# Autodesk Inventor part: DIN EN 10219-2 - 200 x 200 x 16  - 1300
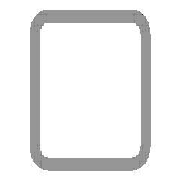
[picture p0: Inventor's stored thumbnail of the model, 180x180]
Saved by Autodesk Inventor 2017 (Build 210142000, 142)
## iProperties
Created: 2017-11
Part Number: DIN EN 10219-2 - 200 x 200 x 16  - 1300
Material: Steel, Mild
Description: Cold formed welded structural hollow sections of non-alloy and fine grain structural steel
Document SubType Name: Modeling
Standard: DIN
Designer: iusti
Standard Revision: 2006-07
Standards Organization: DIN
Language: en-US
Size Designation: 200 x 200 x 16
Categories: <MemberInstance><Categories><Category DisplayName="Structural Shapes" InternalName="089c4875-fa83-4c05-b084-43b9cc11f5ed" Mnemonic="GRDR"><CategoryParameter Dis
Stock Number: 200 x 200 x 16
Mass: 108961 g
Surface Area: 17564.1 cm^2
Volume: 13880.4 cm^3
Density: 7.85 g/cm^3
Appearance: Semi-Polished
G_L: 1300.000 mm
G_W: 200.000 mm
G_H: 200.000 mm
+256F9982-8F43-4545-88E3-061E3400206B+CUTDETAIL1: Cut
+92690F86-3DA3-4326-AD70-C27C8C39E2A5+CUTDETAIL2: Cut
IsCustomPart: 1
_CCFamilyMember: 103
_CCFamilyDisplayName: DIN EN 10219-2 (Square Hollow Section - Cold Formed) - Cold formed welded structural hollow sections of non-alloy and fine grain structural steel
_FrameMemberDoc: Frame Member File
_Version: 15.0.0
_GetPNFromCC: 1
Author: iusti
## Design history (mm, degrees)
node "Start plane"
node "End plane"
sketch "Sketch"
  geometry: L1 (-100, -52)-(-100, 52); L2 (-52, 100)-(52, 100); L3 (100, 52)-(100, -52); L4 (52, -100)-(-52, -100); L5 (-52, 84)-(52, 84); L6 (84, 52)-(84, -52); L7 (52, -84)-(-52, -84); L8 (-84, -52)-(-84, 52); L9 (0, 153.918)-(0, -153.918) reference; L10 (-153.918, 0)-(153.918, 0) reference; A1 r 48 centre (-52, -52) between (-100, -52) and (-52, -100); A2 r 48 centre (-52, 52) between (-52, 100) and (-100, 52); A3 r 48 centre (52, 52) between (100, 52) and (52, 100); A4 r 48 centre (52, -52) between (52, -100) and (100, -52); A5 r 32 centre (-52, 52) between (-52, 84) and (-84, 52); A6 r 32 centre (52, 52) between (84, 52) and (52, 84); A7 r 32 centre (52, -52) between (52, -84) and (84, -52); A8 r 32 centre (-52, -52) between (-84, -52) and (-52, -84)
  constraints: 16 end point, 16 point on circle, 8 centre point, 8 tangent, 4 parallel, 3 equal radius, 2 perpendicular, 7 other
  dimensions: "d7" = 48 radius of A1 (= G_IR); "d10" = 200 distance between parallel lines of L2 L4 (= G_H); "d11" = 200 distance between parallel lines of L1 L3 (= G_W); "d12" = 16 distance between parallel lines of L3 L6 (= G_T); "d15" = 100 distance between parallel lines of L2 L10 (= 0.5 x d10); "d16" = 100 distance between parallel lines of L9 L3 (= 0.5 x d11)
extrude "Body" new body sketch "Sketch" stored distance "d3" = 1300 (= G_L); taper "d4" = 0 deg
node "Driven Length"
  sketch "Sketch3"
    geometry: L1 (0, 0)-(10, 0) reference
    constraints: 2 end point, 1 horizontal
  workplane "Work Plane3"
  sketch "Sketch4"
    geometry: L1 (-2, 100)-(12, 100) reference; L2 (-2, 1400)-(12, 1400) reference
    dimensions: "d18" = 1300 distance between parallel lines of L1 L2 (derived)
workplane "Work Plane4"
split "Split1"
workplane "Work Plane5"
split "Split2"
body "Solid1"
other parameters: "G_W" = 200 [user parameter; used in 1 equation term], "G_H" = 200 [user parameter; used in 1 equation term], "G_T" = 16 [user parameter; used in 1 equation term], "G_IR" = 48 [user parameter; used in 1 equation term], "G_L" = 1300 (= d18) [user parameter; used in 1 equation term], "d17" = 90 deg
